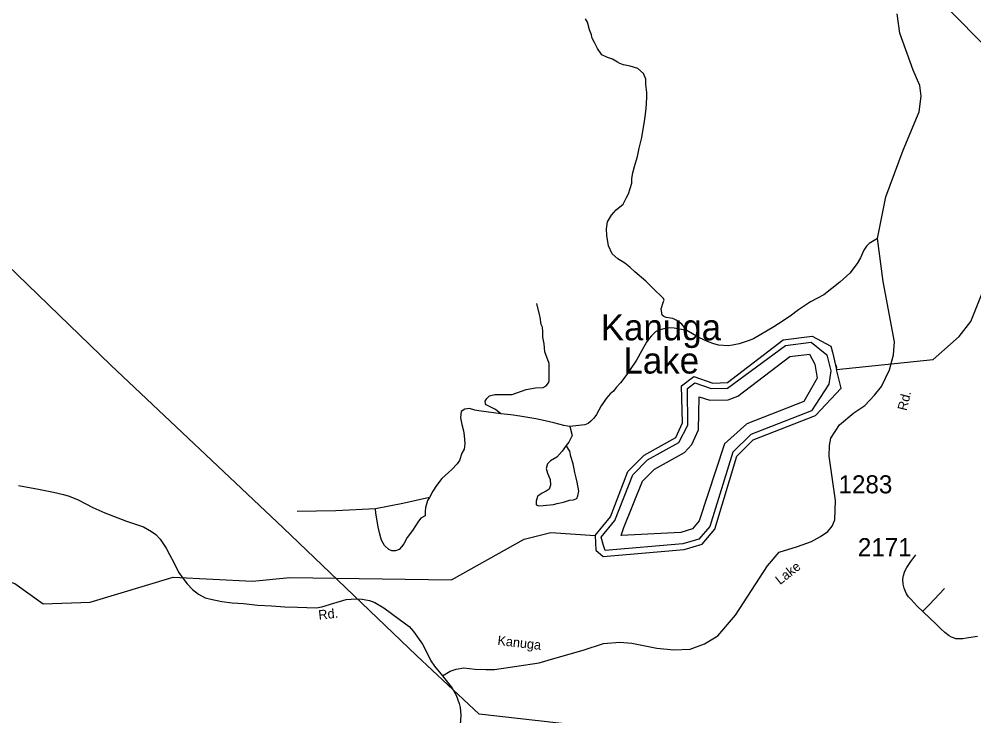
# Model space of a CAD drawing. Extents: x 884530 to 1028605, y 526725 to 653634.
# Drawn here: x 945102 to 951707, y 566865 to 571686 of the extents above; entities that cross this region are included whole.
import ezdxf

# ---------------------------------------------------------------- set-up
doc = ezdxf.new("R2010")
doc.units = 0
for name, color, linetype in [('Exist Hydrographic Bay Label', 7, 'Continuous'), ('Exist Hydrographic Buffer Line', 7, 'Continuous'), ('Exist Hydrographic Creek Single Shore', 7, 'Continuous'), ('Exist Hydrographic Dam on Pond Under 1500 Sq Ft CELL', 7, 'Continuous'), ('Exist Hydrographic Lake Shore Label', 7, 'Continuous'), ('Exist Road Non-System Type 51', 7, 'Continuous'), ('Exist Road Secondary Type 51 Attributed', 7, 'Continuous'), ('Exist Road Secondary Type 51 Label', 7, 'Continuous'), ('Exist Road Secondary Type 51 Number Label', 7, 'Continuous'), ('Exist Utilities Electrical Transmission Line', 7, 'Continuous')]:
    doc.layers.add(name, color=color, linetype=linetype)

msp = doc.modelspace()

# ---------------------------------------------------------------- linework, layer by layer
at = {"layer": 'Exist Hydrographic Bay Label'}
for points in [[(949769.8, 569213.3), (949901.5, 569168), (950001.7, 569172.4), (950387.5, 569466.7), (950588.5, 569492.1), (950718.2, 569423.6), (950727.7, 569381), (950755.5, 569262.4)], [(949088, 568114.5), (949092.7, 568012.7), (949141.3, 567969), (949701.7, 568016.8), (949828, 568053.6), (949915.3, 568157), (950066.7, 568662.5), (950179.1, 568775.2), (950610.5, 568943.7), (950789.2, 569132.5), (950755.5, 569262.4)], [(949088, 568114.5), (949192.8, 568243.7), (949312.5, 568556.3), (949424.9, 568668.9), (949646.1, 568792.4), (949691.4, 568893.2), (949684, 569149.3), (949769.8, 569213.3)]]:
    msp.add_lwpolyline(points, dxfattribs=at)
at = {"layer": 'Exist Hydrographic Buffer Line'}
for points in [[(950716.6, 569252.8), (950704.1, 569161.5), (950583.9, 568976.2), (950164.5, 568812.4), (950038.4, 568690.8), (949879.4, 568176.4), (949805.2, 568088.6), (949694.3, 568056.4), (949155.1, 568010.4), (949145.2, 568044.4), (949128.7, 568101.1), (949223.8, 568218.4), (949346.9, 568534), (949449.3, 568636.7), (949665.6, 568757.5), (949727.9, 568876.8), (949724.6, 569129.7), (949775.4, 569169.8), (949888.5, 569130.2), (950003.4, 569132.5), (950403.2, 569428.4), (950582.2, 569451), (950689.6, 569362.5), (950716.6, 569252.8)], [(950621.5, 569202.5), (950530.8, 569041.4), (950135.4, 568886.9), (949981.7, 568747.3), (949807.5, 568215.3), (949759.6, 568158.7), (949679.6, 568135.4), (949267.4, 568113.3), (949286, 568168.1), (949415.4, 568489.5), (949498, 568572.3), (949704.6, 568687.6), (949755.6, 568743.2), (949800.9, 568844), (949806.2, 569073.9), (949880.7, 569049.8), (950007, 569052.5), (950074.5, 569077), (950434.6, 569351.7), (950569.4, 569368.7), (950605.5, 569298.7), (950621.5, 569202.5)]]:
    msp.add_lwpolyline(points, dxfattribs=at)
at = {"layer": 'Exist Hydrographic Creek Single Shore'}
for points in [[(952404.2, 571053.8), (952380.8, 571106.8), (952009.5, 571209.4), (951834.5, 571449.2), (951488.4, 571797.5), (951262.5, 572238.5), (951249.5, 572573.5), (951085, 572868.9), (951004.4, 573182.2), (950894.2, 573361.7), (950650.9, 573553.6), (950229.5, 573660.5), (950083.1, 573765.2), (949943.4, 573820.5), (949855.5, 573930.6), (949832.1, 574206.7)], [(950755.5, 569262.4), (951425.1, 569331), (951605.8, 569491.4), (951684.7, 569594.8), (952059.8, 570525.8), (952237.6, 570827.4), (952404.2, 571053.8)], [(940411.6, 567540.8), (941431.5, 567612.2), (942295.1, 567739.2), (943513, 567987.1), (943795.6, 567961.7), (944001.9, 567895.2), (944933.2, 567827.3), (945073.5, 567781.8), (945268.5, 567640), (945594.3, 567653.2), (946167.5, 567825.4), (946716.9, 567797.9), (946976.1, 567822.2), (948093, 567806.3), (948595.2, 568088.3), (948780.1, 568133.8), (949088, 568114.5)]]:
    msp.add_lwpolyline(points, dxfattribs=at)
at = {"layer": 'Exist Hydrographic Dam on Pond Under 1500 Sq Ft CELL'}
msp.add_line((950752.4, 569293.1), (950757.2, 569273.3), dxfattribs=at)
msp.add_lwpolyline([(950752.8, 569291.4), (950756.8, 569274.9), (950756.4, 569274.8), (950752.3, 569291.3)], close=True, dxfattribs=at)
at = {"layer": 'Exist Road Non-System Type 51'}
for points in [[(949721.6, 569531.2), (949685.6, 569575.5), (949668.9, 569589), (949646.5, 569604.5), (949624.3, 569615.7), (949578.7, 569622.7), (949562, 569629.4), (949550.2, 569639), (949543.9, 569682.6), (949560.7, 569732.8), (949564.1, 569742.9), (949559.6, 569752.9), (949483.7, 569827.3), (949437.5, 569873.6), (949361.6, 569938.9), (949327.9, 569969.2), (949292.8, 569997.6), (949243.5, 570027.9), (949204.8, 570063.2), (949179, 570118), (949167.6, 570190.1), (949164.8, 570234.7), (949172.4, 570284), (949199.8, 570329.5), (949231.4, 570367.2), (949281.8, 570405.6), (949304, 570451), (949317.6, 570478.3), (949339.5, 570551.8), (949341, 570583.1), (949346.9, 570623.7), (949359.7, 570666.1), (949379.5, 570736.2), (949391.2, 570792.5), (949401.1, 570829.9), (949409, 570868.4), (949416.9, 570911.8), (949428.8, 570978.9), (949437.6, 571048), (949442.5, 571098.2), (949443.5, 571151.6), (949443.5, 571179.2), (949438.6, 571233.4), (949438.6, 571271), (949421.3, 571310.3), (949381.4, 571343.6), (949328.6, 571361.6), (949282.8, 571369.6), (949258.1, 571379.5), (949242.3, 571389.3), (949205.8, 571408.1), (949171.2, 571419.9), (949133.7, 571439.7), (949102.2, 571484.1), (949081.4, 571525.5), (949067.1, 571554.4), (949067, 571554.7), (949064.7, 571563.7), (949060.7, 571578.7), (949048.9, 571613.3), (949033.1, 571665.6), (949021.2, 571689.3)], [(951040.7, 570169.3), (950982.1, 570134.3), (950964.4, 570115.9), (950946.4, 570087.3), (950936.9, 570067.4), (950922.3, 570034.9), (950898.8, 569995.9), (950848, 569929.6), (950779.7, 569867.4), (950668.6, 569779), (950576.4, 569731.1), (950493.1, 569675.6), (950435.2, 569631.2), (950355.9, 569578.9), (950323.5, 569557.6), (950182.6, 569475), (950146, 569459.8), (950084.2, 569439.6), (950036.2, 569429.5), (950007.2, 569425.7), (949939, 569430.8), (949900, 569440.9), (949864.6, 569454.8), (949807.8, 569481.3), (949772.5, 569502.7), (949721.6, 569531.2)], [(948435.3, 568954.7), (948398, 568984.9), (948333.1, 569017.7), (948328, 569023.8), (948325.7, 569041.9), (948338.7, 569062.2), (948357.2, 569078.9), (948392.3, 569088.1), (948460.9, 569090), (948513.5, 569090.1), (948609.8, 569124.1), (948675, 569134.5), (948726.9, 569137.4), (948747.5, 569149.4), (948763.8, 569169.9), (948769.1, 569183.1), (948769, 569261.7), (948769.8, 569303.2), (948738.9, 569383.8), (948734.6, 569439.8), (948726, 569485.8), (948726, 569523.1), (948723.1, 569556.1), (948714.5, 569573.4), (948707.3, 569625.1), (948701.5, 569643.8), (948682.9, 569719.2)], [(949721.6, 569531.2), (949634.4, 569547.5), (949601.7, 569550.3), (949571.8, 569544.9), (949528.2, 569534), (949503.7, 569523.1), (949476.6, 569495.8), (949460.1, 569476.7), (949441.4, 569451.6), (949410.5, 569393.6), (949373, 569327), (949329.4, 569261.6), (949305.6, 569228.4), (949261.3, 569169), (949232.9, 569137.1), (949213.5, 569113.1), (949191, 569092.7), (949179.8, 569080.4), (949163.9, 569060.9), (949149.1, 569040.9), (949128.9, 569009.6), (949095.5, 568950.2), (949077.7, 568925), (949068.9, 568915.1), (949057.5, 568903.7), (949037.7, 568888.9), (949016.4, 568880.4), (948912.2, 568868.2)], [(948435.3, 568954.7), (948281.9, 568976.4), (948255.4, 568981.6), (948218.1, 568992.3), (948186.4, 568986.9), (948159.8, 568971.1), (948154.5, 568928.5), (948165.1, 568880.8), (948175.7, 568838.4), (948181, 568806.5), (948186.4, 568748.1), (948181, 568711), (948165.1, 568684.4), (948149.1, 568631.4), (948133.3, 568610.2), (948096.3, 568571.4), (948027.2, 568508.9), (947990.2, 568459.1), (947964.1, 568421.2), (947940.8, 568376.7)], [(948912.2, 568868.2), (948894.9, 568870.6), (948870.1, 568875.6), (948800.8, 568893), (948741.2, 568907.8), (948676.8, 568920.2), (948565.3, 568940.1), (948503.3, 568947.5), (948435.3, 568954.7)], [(948912.2, 568868.2), (948927.1, 568806.2), (948919.7, 568786.4), (948904.8, 568759.1), (948887, 568736.5)], [(948887, 568736.5), (948859.1, 568697.4), (948822.2, 568656.5), (948777.4, 568630.5), (948756.7, 568609.2), (948748.2, 568577.9), (948756.7, 568545.6), (948775.2, 568501), (948778.9, 568462.6), (948769.1, 568434.7), (948748.7, 568419.5), (948721.4, 568407.2), (948699.1, 568392.3), (948689.2, 568382.4), (948682.8, 568368.3), (948678.1, 568352.2), (948679, 568326.6), (948698, 568319), (948726.5, 568321.8), (948799.3, 568328.3), (948825.1, 568335.1), (948867.5, 568345.2), (948908.5, 568357), (948937.9, 568360.7), (948959.7, 568370.2), (948966.3, 568388.2), (948974, 568421.4), (948961.6, 568482.1), (948954.9, 568512.4), (948945.5, 568549.4), (948940.7, 568576), (948934.1, 568608.8), (948918.6, 568661), (948911.3, 568696.4), (948887, 568736.5)], [(947940.8, 568376.7), (947757, 568335.3), (947568.3, 568297.3)], [(947940.8, 568376.7), (947927.5, 568356.5), (947920.7, 568329.8), (947914, 568306.3), (947910.5, 568279.6), (947910.7, 568249.4)], [(947568.3, 568297.3), (947292.3, 568285.4), (947026.6, 568280.4)], [(947910.7, 568249.4), (947880.5, 568232.6), (947865, 568213.3), (947823.8, 568148.6), (947787.2, 568098.7), (947762.8, 568055.9), (947748.4, 568034.2), (947732.3, 568017.1), (947706.6, 568006.7), (947680.1, 568007.7), (947659.3, 568017.1), (947629.7, 568045.1), (947620.1, 568060.9), (947608.4, 568080.7), (947605.4, 568098.2), (947596.2, 568132.3), (947586.9, 568172.5), (947570.1, 568267.5), (947568.3, 568297.3)], [(951352.8, 567590.1), (951398.4, 567634.6), (951503.6, 567747.5)]]:
    msp.add_lwpolyline(points, dxfattribs=at)
at = {"layer": 'Exist Road Secondary Type 51 Attributed'}
for points in [[(948031.8, 567141.8), (948084.7, 567173.9), (948124.8, 567189.8), (948179.1, 567198.1), (948257.6, 567189.8), (948330.3, 567186.4), (948390.5, 567185.6), (948700, 567232.6), (948801.8, 567262.4), (949004, 567320.8), (949144.3, 567365.5), (949257.2, 567375.4), (949341.6, 567367.9), (949514, 567333.2), (949630.7, 567322), (949744, 567326.3), (949844.1, 567363), (949936.4, 567419.8), (950057.4, 567562.8), (950279.7, 567903.6), (950359.8, 567997.4), (950486.9, 568038.3), (950583.7, 568073), (950644.5, 568106.5), (950695.4, 568141.3), (950726.4, 568178.5), (950744.6, 568223), (950750.1, 568355), (950706.1, 568663.1), (950707.8, 568735.9), (950717.7, 568788.1), (950776.1, 568879.9), (950876.1, 568963.4), (950952.3, 569012.1), (951019, 569084.5), (951067.7, 569144.9), (951123.5, 569260.5), (951149.6, 569363.4), (951156.4, 569453), (951079.5, 569871.1), (951040.7, 570169.3), (951097.5, 570455.8), (951217.8, 570779.8), (951328.3, 571044.8), (951341.9, 571154.1), (951332.3, 571227.3), (951287.3, 571334.1), (951195.5, 571589.8), (951175.6, 571722.6)], [(945099, 568458.8), (945236.1, 568434.6), (945340.1, 568412.4), (945409.5, 568397.4), (945448.7, 568385.7), (945511.4, 568359.8), (945612.7, 568307.8), (945694.8, 568269.9), (945755, 568246.5), (945844.8, 568213.9), (945963.5, 568172.5), (946018.6, 568142.4), (946047.9, 568120.7), (946077.1, 568087.2), (946119.2, 568024.9), (946143, 567981.7), (946171.7, 567926.1), (946205.7, 567860.2), (946235.5, 567818.2), (946264, 567778.6), (946301.9, 567740.3), (946342.8, 567708.5), (946389.6, 567681.8), (946429.3, 567672.2), (946504.5, 567657.9), (946577.2, 567648.8), (946654.9, 567642.9), (946754.8, 567632.4), (946848.4, 567626.6), (946941.1, 567620.7), (947027.3, 567618.6), (947156.3, 567613.6), (947196.4, 567621.2), (947278.6, 567646.3), (947363.9, 567670.1), (947433.3, 567674.3), (947474.2, 567672.6), (947526.1, 567664.2), (947562.8, 567650), (947625.5, 567614.1), (947732, 567535.1), (947799.7, 567484.1), (947831.5, 567448.9), (947892.1, 567361.6), (947928.8, 567289.7), (947949.7, 567246.2), (947974.8, 567210.3), (948031.8, 567141.8)], [(951732.5, 567415), (951698.2, 567409.6), (951654.8, 567402.8), (951630.8, 567399.3), (951610.9, 567397.6), (951598.9, 567397.6), (951581.2, 567399.6), (951566.1, 567404.5), (951551.5, 567410.5), (951535.8, 567419), (951504.7, 567442.4), (951475, 567469.6), (951442.8, 567501.5), (951313.9, 567625.4), (951272.5, 567670.6), (951253.3, 567690.2), (951240, 567709.8), (951233.2, 567725.6), (951223.8, 567749.1), (951217, 567776.4), (951216.2, 567810.5), (951219.1, 567836.9), (951229.8, 567866.4), (951242.2, 567892), (951271.2, 567934.6), (951304.4, 567980.2)], [(948031.8, 567141.8), (948098.9, 567056.9), (948124.8, 567010), (948146.9, 566951.1), (948154, 566923.9), (948157.4, 566871.3), (948147.6, 566739.7)]]:
    msp.add_lwpolyline(points, dxfattribs=at)
at = {"layer": 'Exist Utilities Electrical Transmission Line'}
for points in [[(945735.9, 569292.4), (944511.8, 570474.8), (943313.9, 571626.5), (942530.7, 573100.6), (941761.7, 574594.1), (941063.9, 576120.3), (940393.7, 577647.3), (939830.8, 578620.8), (939001, 579373.9), (938802.7, 579433), (937171.8, 579811), (935544.6, 580195.5), (933918.8, 580578.7), (932267.9, 580954.5), (931153.7, 581033.3), (928415.8, 581209.1), (925643.8, 581364.6), (922305, 580117.8), (921595.1, 579498.2)], [(952962.7, 564845.5), (951594.8, 565377), (949793.8, 566707.6), (948284.7, 566877.1), (947850.8, 567283.5), (946927.8, 568165.8), (945735.9, 569292.4)]]:
    msp.add_lwpolyline(points, dxfattribs=at)

# ---------------------------------------------------------------- texts
at = {"layer": 'Exist Hydrographic Lake Shore Label'}
for s, p in [('Kanuga', (949125.8, 569463.9)), ('Kanuga', (949125.8, 569463.9)), ('Lake', (949282.6, 569234.2)), ('Lake', (949282.6, 569234.2))]:
    msp.add_text(s, height=180.45, dxfattribs=at).set_placement(p)
at = {"layer": 'Exist Road Secondary Type 51 Label'}
for s, rotation, p in [('Rd.', 75.97632, (951240.5, 568972.8)), ('Lake', 38.31448, (950365.7, 567769.6)), ('Rd.', 6.30414, (947176.2, 567530.6)), ('Kanuga', 353.36183, (948408.7, 567357))]:
    msp.add_text(s, height=65.62, rotation=rotation, dxfattribs=at).set_placement(p)
at = {"layer": 'Exist Road Secondary Type 51 Number Label'}
for s, p in [('1283', (950770.5, 568405.3)), ('2171', (950904.3, 567970.5))]:
    msp.add_text(s, height=125, dxfattribs=at).set_placement(p)

doc.saveas('drawing.dxf')
